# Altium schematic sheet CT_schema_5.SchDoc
size 454 x 430 mm
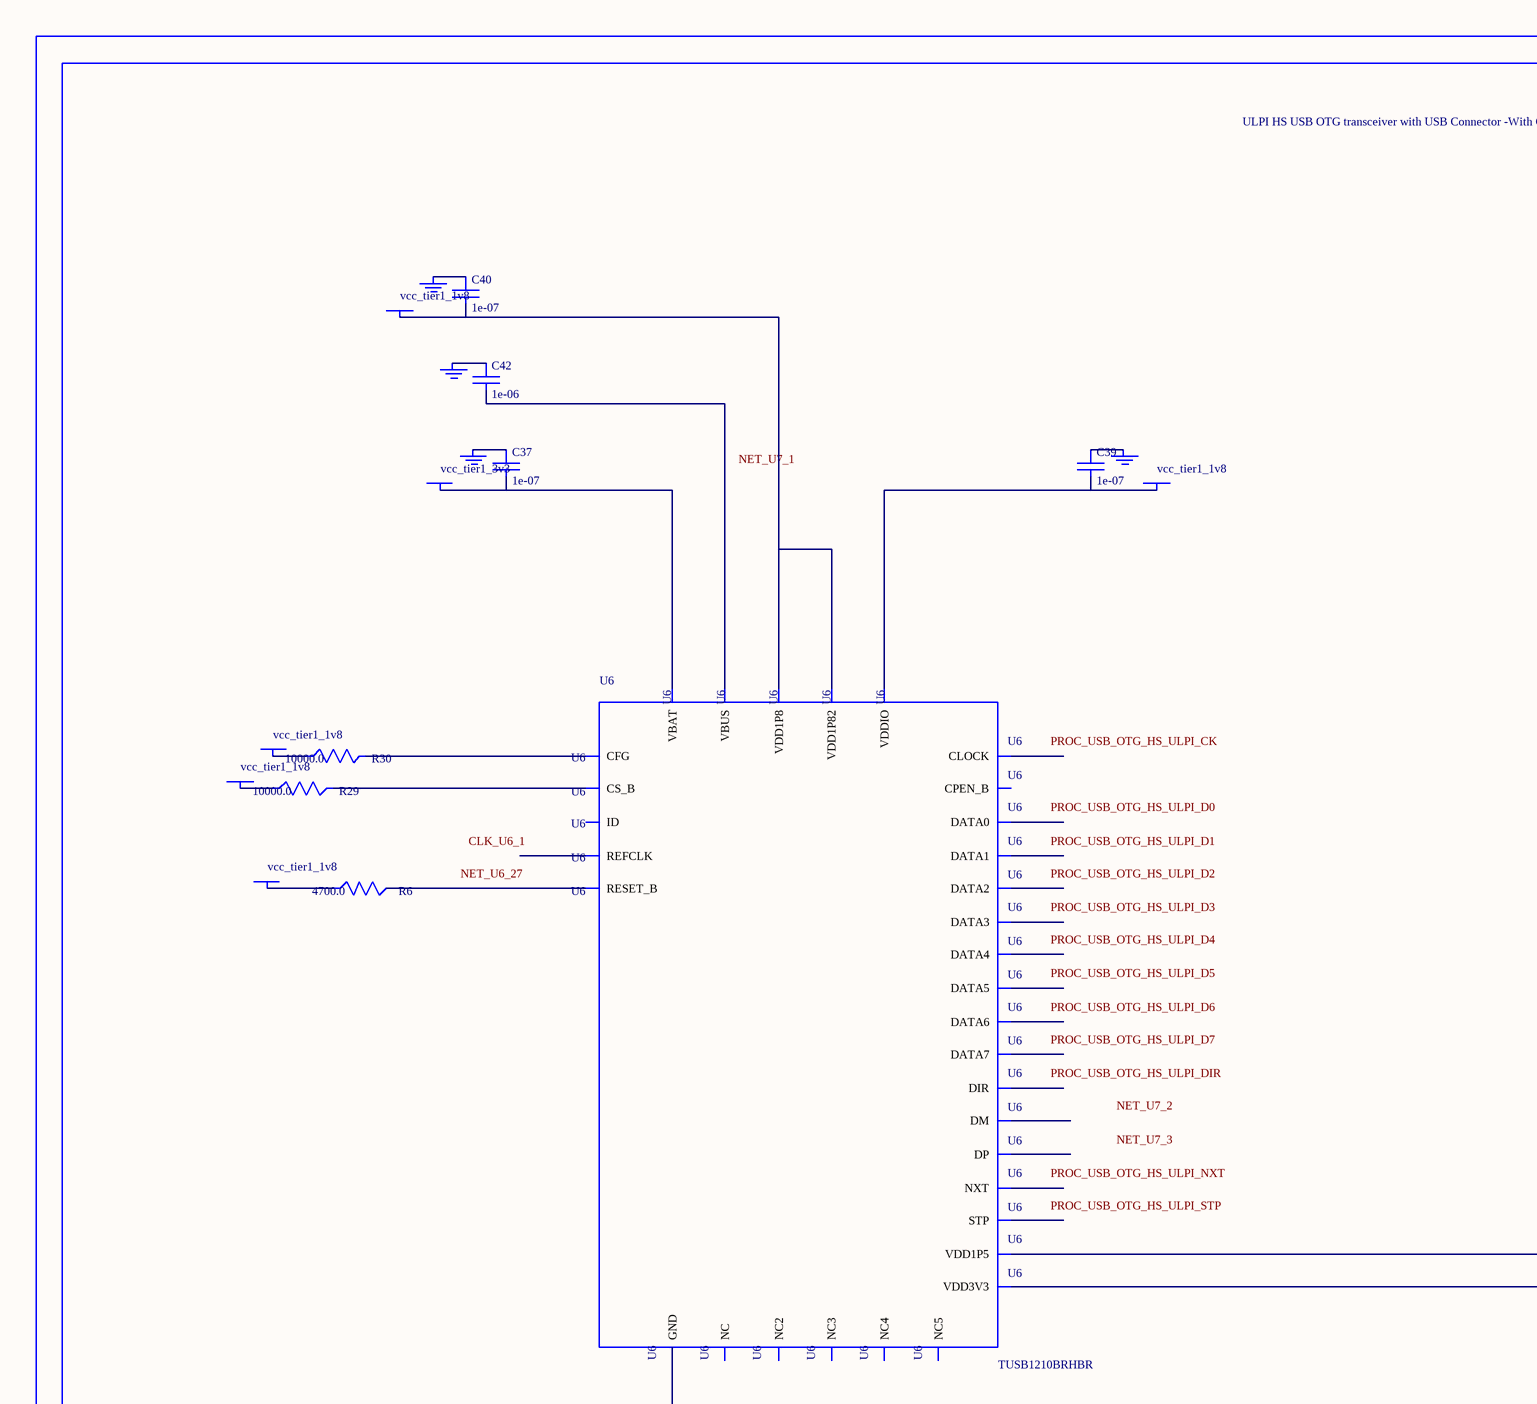
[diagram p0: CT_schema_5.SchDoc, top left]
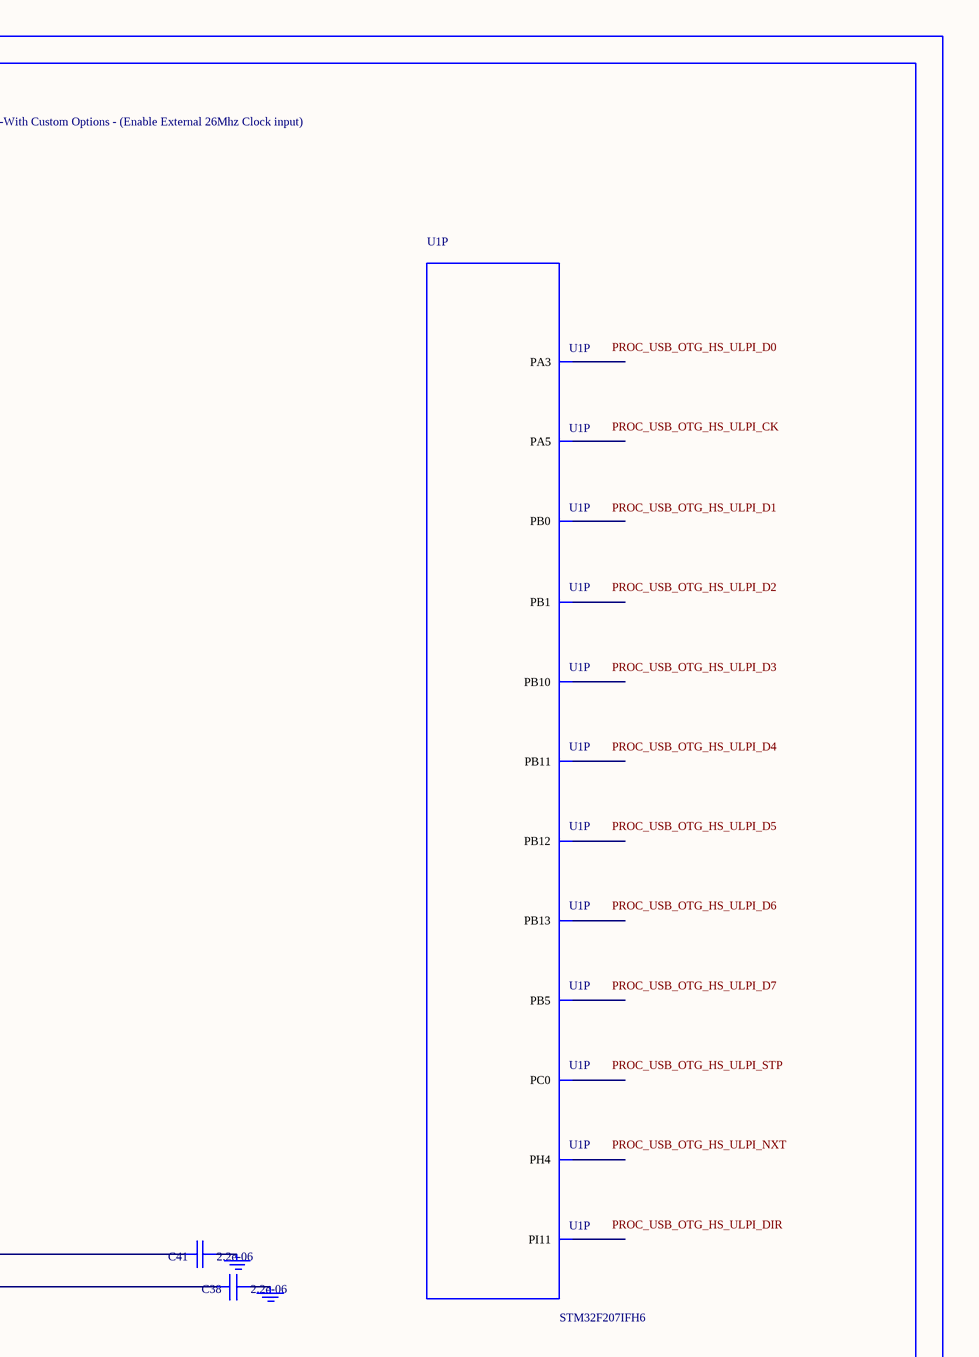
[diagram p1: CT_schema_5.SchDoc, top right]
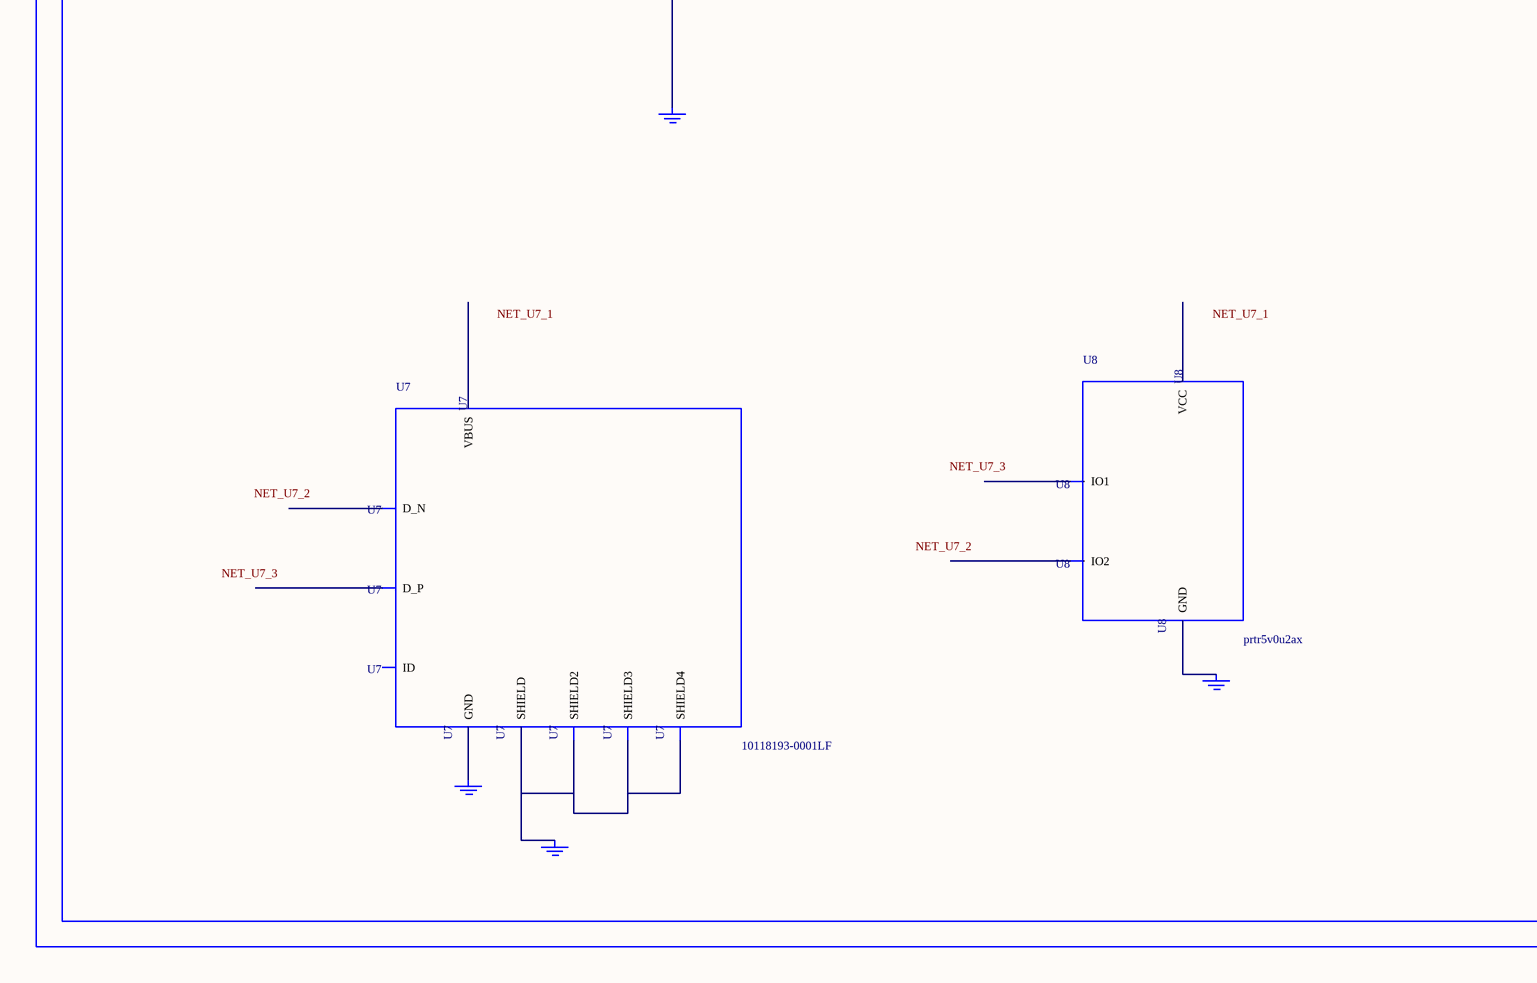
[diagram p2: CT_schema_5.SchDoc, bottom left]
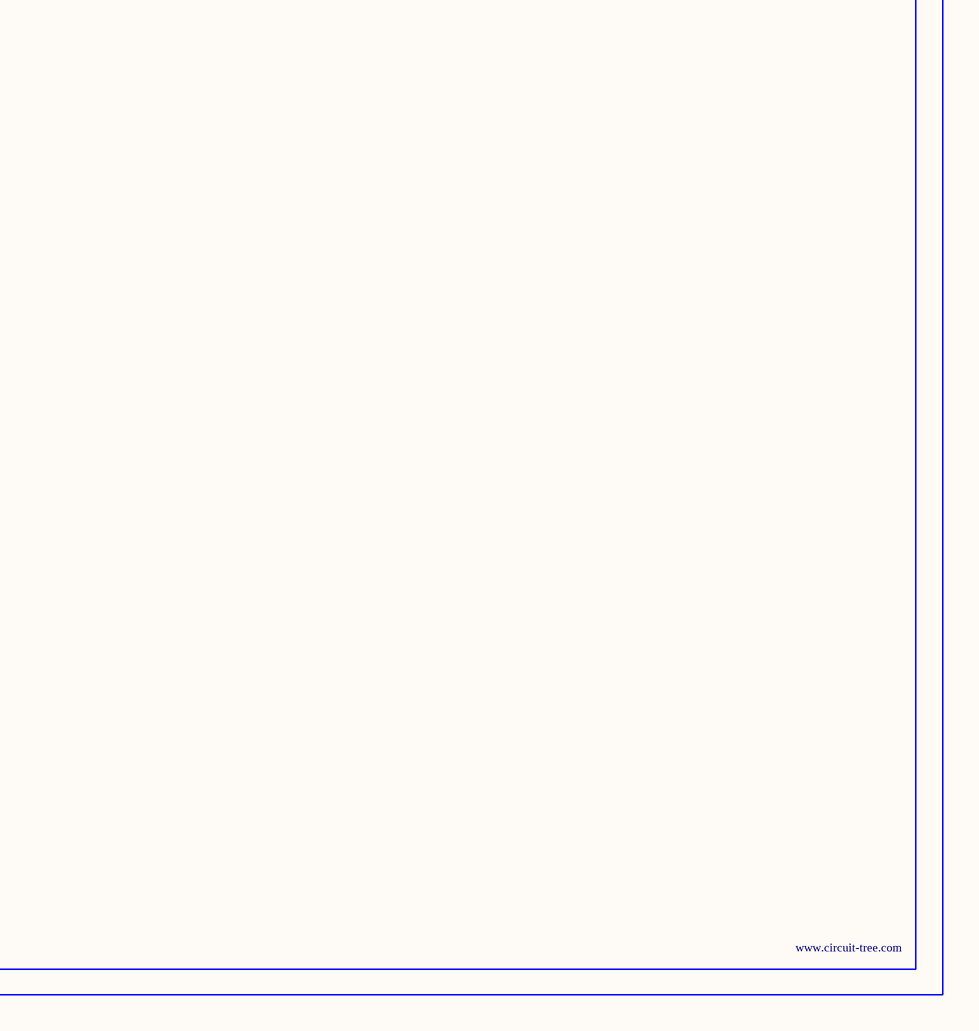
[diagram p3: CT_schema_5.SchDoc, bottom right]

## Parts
BORDER4  (no value)
C37  1e-07  [C0402]
C38  2.2e-06  [C0603]
C39  1e-07  [C0402]
C40  1e-07  [C0402]
C41  2.2e-06  [C0603]
C42  1e-06  [C0603]
GND_INSTANCE_4_0  (no value)
GND_INSTANCE_4_1  (no value)
GND_INSTANCE_4_2  (no value)
GND_INSTANCE_4_3  (no value)
GND_INSTANCE_4_4  (no value)
GND_INSTANCE_4_5  (no value)
GND_INSTANCE_4_6  (no value)
GND_INSTANCE_4_7  (no value)
GND_INSTANCE_4_8  (no value)
GND_INSTANCE_4_9  (no value)
POWER_INSTANCE_4_0  vcc_tier1_1v8
POWER_INSTANCE_4_1  vcc_tier1_1v8
POWER_INSTANCE_4_2  vcc_tier1_3v3
POWER_INSTANCE_4_3  vcc_tier1_1v8
POWER_INSTANCE_4_4  vcc_tier1_1v8
POWER_INSTANCE_4_5  vcc_tier1_1v8
R6  4700.0  [R0603]
R29  10000.0  [R0603]
R30  10000.0  [R0603]
U1  STM32F207IFH6  [UFBGA176_25]  (part P of 16)
U6  TUSB1210BRHBR  [RHB32_3P45X3P45]
U7  10118193-0001LF  [FCI_10118193-0001LF]
U8  prtr5v0u2ax  [SOT143B]

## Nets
NetC37_1: C37.1 GND_INSTANCE_4_2.0(GND)
NetC37_2: C37.2 POWER_INSTANCE_4_2.0(PWR) U6.21(VBAT)
NetC38_1: C38.1 GND_INSTANCE_4_1.0(GND)
NetC38_2: C38.2 U6.20(VDD3V3)
NetC39_1: C39.1 GND_INSTANCE_4_5.0(GND)
NetC39_2: C39.2 POWER_INSTANCE_4_4.0(PWR) U6.32(VDDIO)
NetC40_1: C40.1 GND_INSTANCE_4_4.0(GND)
NetC40_2: C40.2 POWER_INSTANCE_4_3.0(PWR) U6.28(VDD1P8) U6.30(VDD1P82)
NetC41_1: C41.1 GND_INSTANCE_4_0.0(GND)
NetC41_2: C41.2 U6.12(VDD1P5)
NetC42_1: C42.1 GND_INSTANCE_4_3.0(GND)
NetC42_2: C42.2 U6.22(VBUS)
NetGND_INSTANCE_4_6_0: GND_INSTANCE_4_6.0(GND) U6.33(GND)
NetGND_INSTANCE_4_7_0: GND_INSTANCE_4_7.0(GND) U7.6(SHIELD) U7.7(SHIELD2) U7.8(SHIELD3) U7.9(SHIELD4)
NetGND_INSTANCE_4_8_0: GND_INSTANCE_4_8.0(GND) U7.5(GND)
NetGND_INSTANCE_4_9_0: GND_INSTANCE_4_9.0(GND) U8.1(GND)
NetPOWER_INSTANCE_4_0_0: POWER_INSTANCE_4_0.0(PWR) R29.1
NetPOWER_INSTANCE_4_1_0: POWER_INSTANCE_4_1.0(PWR) R30.1
NetPOWER_INSTANCE_4_5_0: POWER_INSTANCE_4_5.0(PWR) R6.1
NetR6_2: R6.2 U6.27(RESET_B)
NetR29_2: R29.2 U6.11(CS_B)
NetR30_2: R30.2 U6.14(CFG)

Not connected (* = marked no-connect by the designer): U1 A6(PB5) E4(PI11) H4(PH4) M2(PC0) P4(PA5) P12(PB12) P13(PB13) R2(PA3) R4(PB1) R5(PB0) R12(PB10) R13(PB11); U6 1(REFCLK) 2(NXT) 3(DATA0) 4(DATA1) 5(DATA2) 6(DATA3) 7(DATA4) 8(NC) 9(DATA5) 10(DATA6) 13(DATA7) 15(NC2) 16(NC3) 17(CPEN_B) 18(DP) 19(DM) 23(ID) 24(NC4) 25(NC5) 26(CLOCK) 29(STP) 31(DIR); U7 1(VBUS) 2(D_N) 3(D_P) 4(ID); U8 2(IO1) 3(IO2) 4(VCC)

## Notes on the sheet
- Labels drawn without touching a wire or pin: CLK_U6_1, NET_U6_27, NET_U7_1, NET_U7_2, NET_U7_3, PROC_USB_OTG_HS_ULPI_CK, PROC_USB_OTG_HS_ULPI_D0, PROC_USB_OTG_HS_ULPI_D1, PROC_USB_OTG_HS_ULPI_D2, PROC_USB_OTG_HS_ULPI_D3, PROC_USB_OTG_HS_ULPI_D4, PROC_USB_OTG_HS_ULPI_D5, PROC_USB_OTG_HS_ULPI_D6, PROC_USB_OTG_HS_ULPI_D7, PROC_USB_OTG_HS_ULPI_DIR, PROC_USB_OTG_HS_ULPI_NXT, PROC_USB_OTG_HS_ULPI_STP

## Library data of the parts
BORDER4 = BORDER_PAGE4
C37 C39 C40 = C0402C104K3RACTU
C38 C41 = C0603C225K8RACTU
C42 = C0603C105K3RACTU
GND_INSTANCE_4_0-GND_INSTANCE_4_9 = GND
POWER_INSTANCE_4_0-POWER_INSTANCE_4_5 = PWR
R6 = RC0603JR-074K7L
R29 R30 = RC0603JR-0710KL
